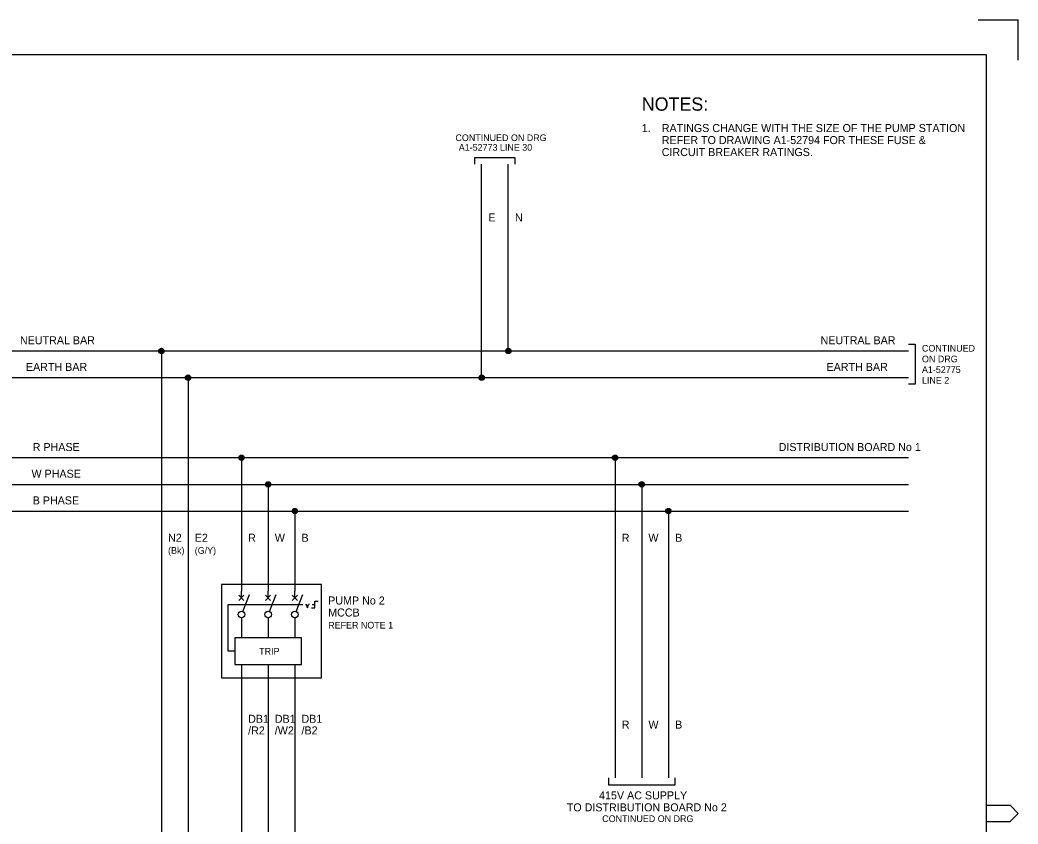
# Model space of a CAD drawing. Extents: x 0 to 841, y 0 to 594.
# Drawn here: x 467 to 841, y 292.8 to 594 of the extents above; entities that cross this region are included whole.
import ezdxf

# ---------------------------------------------------------------- set-up
doc = ezdxf.new("R2010")
doc.units = 0
for name, color, linetype in [('A1BORDER', 7, 'Continuous'), ('Level 1', 7, 'Continuous'), ('Level 10', 7, 'Continuous')]:
    doc.layers.add(name, color=color, linetype=linetype)

msp = doc.modelspace()

# ---------------------------------------------------------------- linework, layer by layer
at = {"layer": 'A1BORDER'}
for p, q in [((826, 594), (841, 594)), ((841, 579), (841, 594)), ((28, 581), (829, 581)), ((829, 581), (829, 15)), ((829, 299.76), (838, 299.76)), ((838, 299.76), (841, 296.76)), ((838, 293.76), (841, 296.76)), ((829, 293.76), (838, 293.76))]:
    msp.add_line(p, q, dxfattribs=at)
at = {"layer": 'Level 1'}
for p, q in [((640, 460), (640, 540)), ((650, 470), (650, 540)), ((50, 470), (800, 470)), ((520, 470), (520, 120)), ((50, 460), (800, 460)), ((530, 460), (530, 120)), ((800, 430), (50, 430)), ((550, 430), (550, 380)), ((690, 430), (690, 310.00001)), ((50, 420), (800, 420)), ((560, 420), (560, 380)), ((700, 420), (700, 310.00001)), ((50, 410), (800, 410)), ((570, 410), (570, 380)), ((710, 410), (710, 310.00001)), ((549.06, 378.44), (550.94, 376.56)), ((550.94, 378.44), (549.06, 376.56)), ((550, 377.5), (550, 380)), ((550.46, 372.41), (553, 378.75)), ((559.06, 378.44), (560.94, 376.56)), ((560.94, 378.44), (559.06, 376.56)), ((560, 377.5), (560, 380)), ((560.46, 372.41), (563, 378.75)), ((569.06, 378.44), (570.94, 376.56)), ((570.94, 378.44), (569.06, 376.56)), ((570, 377.5), (570, 380)), ((570.46, 372.41), (573, 378.75)), ((545, 357.5), (545, 375)), ((545, 375), (551.5, 375)), ((551.5, 375), (571.5, 375)), ((550, 370), (550, 362.5)), ((560, 370), (560, 362.5)), ((570, 370), (570, 362.5)), ((547.5, 357.5), (545, 357.5)), ((550, 352.5), (550, 120)), ((560, 352.5), (560, 120)), ((570, 352.5), (570, 120))]:
    msp.add_line(p, q, dxfattribs=at)
for points in [[(637.5, 540), (637.5, 542.5), (652.5, 542.5), (652.5, 540)], [(800, 472.5), (802.5, 472.5), (802.5, 457.5), (800, 457.5)], [(687.5, 310.00001), (687.5, 307.50001), (712.5, 307.50001), (712.5, 310.00001)]]:
    msp.add_lwpolyline(points, dxfattribs=at)
for points in [[(580, 382.5), (542.5, 382.5), (542.5, 347.5), (580, 347.5)], [(547.5, 352.5), (572.5, 352.5), (572.5, 362.5), (547.5, 362.5)]]:
    msp.add_lwpolyline(points, close=True, dxfattribs=at)
for centre in [(550, 371.25), (560, 371.25), (570, 371.25)]:
    msp.add_circle(centre, 1.25, dxfattribs=at)
at = {"layer": 'Level 10'}
for p, q in [((519.01, 470.1), (520.99, 470.1)), ((519.02, 469.8), (520.98, 469.8)), ((519.08, 470.4), (520.92, 470.4)), ((519.13, 469.5), (520.87, 469.5)), ((519.29, 470.7), (520.71, 470.7)), ((519.4, 469.2), (520.6, 469.2)), ((520, 471), (520, 471)), ((649.01, 470.1), (650.99, 470.1)), ((649.02, 469.8), (650.98, 469.8)), ((649.08, 470.4), (650.92, 470.4)), ((649.13, 469.5), (650.87, 469.5)), ((649.29, 470.7), (650.71, 470.7)), ((649.4, 469.2), (650.6, 469.2)), ((650, 471), (650, 471)), ((529.01, 460.1), (530.99, 460.1)), ((529.08, 460.4), (530.92, 460.4)), ((529.29, 460.7), (530.71, 460.7)), ((530, 461), (530, 461)), ((639.01, 460.1), (640.99, 460.1)), ((639.08, 460.4), (640.92, 460.4)), ((639.29, 460.7), (640.71, 460.7)), ((640, 461), (640, 461)), ((529.02, 459.8), (530.98, 459.8)), ((529.13, 459.5), (530.87, 459.5)), ((529.4, 459.2), (530.6, 459.2)), ((639.02, 459.8), (640.98, 459.8)), ((639.13, 459.5), (640.87, 459.5)), ((639.4, 459.2), (640.6, 459.2)), ((549.01, 430.1), (550.99, 430.1)), ((549.08, 430.4), (550.92, 430.4)), ((549.29, 430.7), (550.71, 430.7)), ((550, 431), (550, 431)), ((689.01, 430.1), (690.99, 430.1)), ((689.08, 430.4), (690.92, 430.4)), ((689.29, 430.7), (690.71, 430.7)), ((690, 431), (690, 431)), ((549.02, 429.8), (550.98, 429.8)), ((549.13, 429.5), (550.87, 429.5)), ((549.4, 429.2), (550.6, 429.2)), ((689.02, 429.8), (690.98, 429.8)), ((689.13, 429.5), (690.87, 429.5)), ((689.4, 429.2), (690.6, 429.2)), ((559.01, 420.1), (560.99, 420.1)), ((559.02, 419.8), (560.98, 419.8)), ((559.08, 420.4), (560.92, 420.4)), ((559.13, 419.5), (560.87, 419.5)), ((559.29, 420.7), (560.71, 420.7)), ((559.4, 419.2), (560.6, 419.2)), ((560, 421), (560, 421)), ((699.01, 420.1), (700.99, 420.1)), ((699.02, 419.8), (700.98, 419.8)), ((699.08, 420.4), (700.92, 420.4)), ((699.13, 419.5), (700.87, 419.5)), ((699.29, 420.7), (700.71, 420.7)), ((699.4, 419.2), (700.6, 419.2)), ((700, 421), (700, 421)), ((569.01, 410.1), (570.99, 410.1)), ((569.02, 409.8), (570.98, 409.8)), ((569.08, 410.4), (570.92, 410.4)), ((569.13, 409.5), (570.87, 409.5)), ((569.29, 410.7), (570.71, 410.7)), ((569.4, 409.2), (570.6, 409.2)), ((570, 411), (570, 411)), ((709.01, 410.1), (710.99, 410.1)), ((709.02, 409.8), (710.98, 409.8)), ((709.08, 410.4), (710.92, 410.4)), ((709.13, 409.5), (710.87, 409.5)), ((709.29, 410.7), (710.71, 410.7)), ((709.4, 409.2), (710.6, 409.2)), ((710, 411), (710, 411)), ((571.5, 375), (573, 375)), ((574, 375), (574.33, 375)), ((574.75, 373.75), (574.33, 375)), ((574.75, 373.75), (575.17, 375)), ((575.5, 375), (575.17, 375)), ((576.5, 375), (577.5, 375)), ((577.5, 373.75), (577.5, 376.25)), ((577.5, 376.25), (578.75, 376.25)), ((576.25, 373.75), (577.5, 373.75))]:
    msp.add_line(p, q, dxfattribs=at)
for centre in [(520, 470), (650, 470), (530, 460), (640, 460), (550, 430), (690, 430), (560, 420), (700, 420), (570, 410), (710, 410)]:
    msp.add_circle(centre, 1, dxfattribs=at)

# ---------------------------------------------------------------- texts
at = {"layer": 'Level 1'}
for s, height, p in [('NOTES:', 5, (700, 560)), ('1.', 3, (700, 552)), ('RATINGS CHANGE WITH THE SIZE OF THE PUMP STATION', 3, (707.5, 552)), ('CONTINUED ON DRG', 2.50002, (630.18299, 548.61819)), ('REFER TO DRAWING A1-52794 FOR THESE FUSE &', 3, (707.5, 547.5)), ('A1-52773 LINE 30', 2.50002, (631.42811, 545)), ('CIRCUIT BREAKER RATINGS.', 3, (707.5, 543)), ('E', 3, (642.5, 518.49999)), ('N', 3, (652.5, 518.49999)), ('NEUTRAL BAR', 3, (467.00098, 472.5)), ('NEUTRAL BAR', 3, (767.00098, 472.5)), ('CONTINUED', 2.5, (805, 469.75)), ('ON DRG', 2.5, (805, 465.75)), ('EARTH BAR', 3, (469.23746, 462.5)), ('EARTH BAR', 3, (769.23746, 462.5)), ('A1-52775', 2.5, (805, 461.75)), ('LINE 2', 2.5, (805, 457.75)), ('R PHASE', 3, (471.78289, 432.5)), ('DISTRIBUTION BOARD No 1', 3, (751.29168, 432.5)), ('W PHASE', 3, (471.32759, 422.5)), ('B PHASE', 3, (471.78289, 412.5)), ('N2', 3, (522.5, 398.49999)), ('E2', 3, (532.5, 398.49999)), ('R', 3, (552.5, 398.49999)), ('W', 3, (562.5, 398.49999)), ('B', 3, (572.5, 398.49999)), ('R', 3, (692.5, 398.49999)), ('W', 3, (702.5, 398.49999)), ('B', 3, (712.5, 398.49999)), ('(Bk)', 2.50002, (522.5, 393.99998)), ('(G/Y)', 2.50002, (532.5, 393.99998)), ('PUMP No 2', 3, (582.5, 375)), ('MCCB', 3, (582.5, 370.5)), ('REFER NOTE 1', 2.50002, (582.5, 365.99998)), ('DB1', 3, (552.5, 330.67089)), ('DB1', 3, (562.5, 330.67089)), ('DB1', 3, (572.5, 330.67089)), ('/R2', 3, (552.5, 326.32909)), ('/W2', 3, (562.5, 326.32909)), ('/B2', 3, (572.5, 326.32909)), ('R', 3, (692.5, 328.5)), ('W', 3, (702.5, 328.5)), ('B', 3, (712.5, 328.5)), ('415V AC SUPPLY', 3, (684.0127, 302.00001)), ('TO DISTRIBUTION BOARD No 2', 3, (671.91016, 297.50001)), ('CONTINUED ON DRG', 2.50002, (685.18299, 293.49999))]:
    msp.add_text(s, height=height, dxfattribs=at).set_placement(p)
msp.add_text('TRIP', height=2.50002, rotation=360, dxfattribs=at).set_placement((556.64328, 356.25))

doc.saveas('drawing.dxf')
